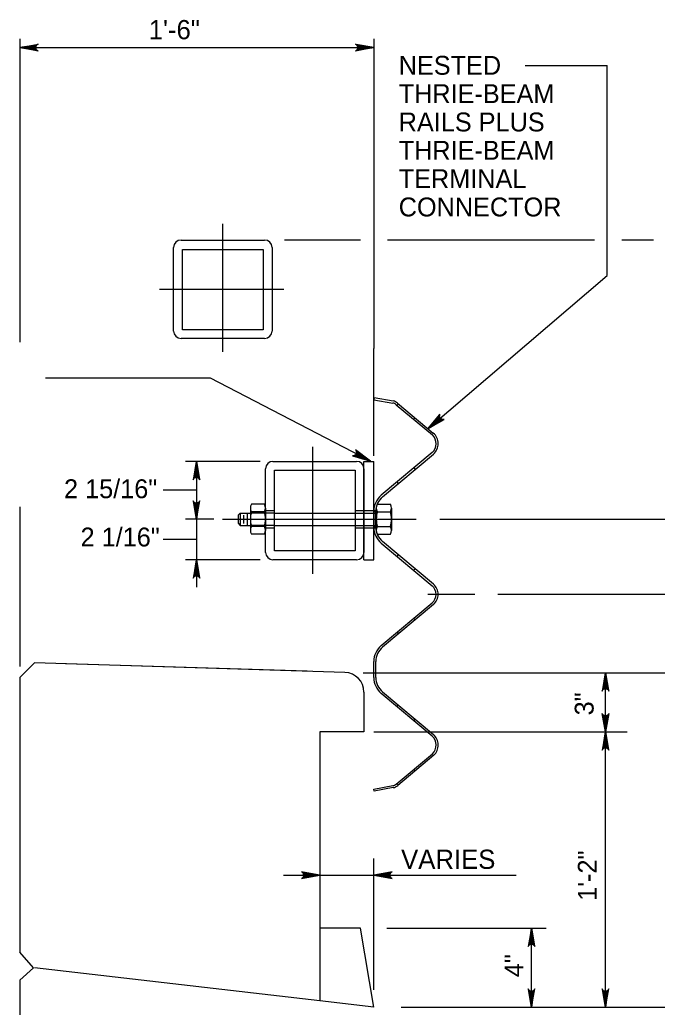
# Model space of a CAD drawing. Extents: x 632007860 to 635435983, y 295418622 to 297794622.
# Drawn here: x 633825946 to 633928846, y 296133282 to 296292631 of the extents above; entities that cross this region are included whole.
import ezdxf

# ---------------------------------------------------------------- set-up
doc = ezdxf.new("R2010")
doc.units = 0
for name, color, linetype in [('8', 7, 'Continuous'), ('S-ABUT', 7, 'Continuous'), ('S-DECK', 7, 'Continuous'), ('S-DETL-DIMS', 7, 'Continuous'), ('S-DETL-T120', 7, 'Continuous'), ('S-STEL', 7, 'Continuous')]:
    doc.layers.add(name, color=color, linetype=linetype)

msp = doc.modelspace()

# ---------------------------------------------------------------- linework, layer by layer
at = {"layer": '8'}
for p, q in [((633858727, 296239031), (633858727, 296259693)), ((633848498, 296249148), (633868578, 296249148)), ((633873268, 296203219), (633873268, 296223704)), ((633858691, 296212039), (633889941, 296212039)), ((633891801, 296199934), (633899397, 296199934))]:
    msp.add_line(p, q, dxfattribs=at)
at = {"layer": 'S-ABUT'}
for p, q in [((633828181, 296139661), (633825946, 296142171)), ((633825946, 296137671), (633828181, 296139661))]:
    msp.add_line(p, q, dxfattribs=at)
at = {"layer": 'S-DECK'}
for p, q in [((633828327, 296188859), (633825946, 296186477)), ((633878430, 296187309), (633828327, 296188859)), ((633825946, 296186477), (633825946, 296142171)), ((633881507, 296184136), (633881507, 296177732)), ((633874364, 296177732), (633874364, 296134296)), ((633881507, 296177732), (633874364, 296177732)), ((633880967, 296146039), (633874364, 296146039)), ((633883096, 296133282), (633880967, 296146039)), ((633874364, 296134296), (633828322, 296139645)), ((633825946, 296137671), (633825946, 296107186)), ((633883096, 296133282), (633874364, 296134296))]:
    msp.add_line(p, q, dxfattribs=at)
msp.add_arc((633878332, 296184136), 3175, 0, 88.22879, dxfattribs=at)
at = {"layer": 'S-DETL-DIMS'}
for p, q in [((633825946, 296289555), (633825946, 296268629)), ((633883096, 296289555), (633883096, 296239608)), ((633825946, 296288136), (633883096, 296288136)), ((633907523, 296285254), (633920786, 296285254)), ((633920786, 296251347), (633920786, 296285254)), ((633825946, 296268629), (633825946, 296240593)), ((633868663, 296257107), (633880958, 296257107)), ((633885291, 296257107), (633918740, 296257107)), ((633923144, 296257107), (633928239, 296257107)), ((633891854, 296226649), (633920786, 296251347)), ((633883094, 296222253), (633883094, 296239608)), ((633856711, 296234769), (633830120, 296234769)), ((633882538, 296221399), (633856711, 296234769)), ((633864738, 296221365), (633852720, 296221365)), ((633854466, 296221365), (633854466, 296201053)), ((633854466, 296216706), (633849079, 296216706)), ((633825946, 296214055), (633825946, 296188241)), ((633857273, 296212039), (633852720, 296212039)), ((633893768, 296212039), (633934041, 296212039)), ((633854466, 296208765), (633849079, 296208765)), ((633864738, 296205489), (633852720, 296205489)), ((633903112, 296199957), (633961692, 296199957)), ((633913164, 296199957), (633932328, 296199957)), ((633881361, 296187270), (633955531, 296187270)), ((633920483, 296133282), (633920483, 296187270)), ((633883096, 296177732), (633923989, 296177732)), ((633883096, 296136074), (633883096, 296157302)), ((633868536, 296154603), (633883096, 296154603)), ((633885675, 296154603), (633906053, 296154603)), ((633885176, 296146039), (633910942, 296146039)), ((633908544, 296133282), (633908544, 296146039)), ((633887495, 296133282), (633986864, 296133282))]:
    msp.add_line(p, q, dxfattribs=at)
for points in [[(633825946, 296288136), (633828905, 296288691), (633828791, 296288612), (633828677, 296288533), (633828618, 296288433), (633828559, 296288334), (633828542, 296288235), (633828525, 296288136), (633828542, 296288036), (633828559, 296287937), (633828618, 296287838), (633828677, 296287739), (633828791, 296287660), (633828905, 296287581), (633825946, 296288136), (633828791, 296287660), (633828677, 296287739), (633825946, 296288136), (633828618, 296287838), (633828559, 296287937), (633825946, 296288136), (633828542, 296288036), (633828525, 296288136), (633825946, 296288136), (633828542, 296288235), (633828559, 296288334), (633825946, 296288136), (633828618, 296288433), (633828677, 296288533), (633825946, 296288136), (633828791, 296288612)], [(633883096, 296288136), (633880137, 296287581), (633880251, 296287660), (633880365, 296287739), (633880424, 296287838), (633880483, 296287937), (633880500, 296288036), (633880517, 296288136), (633880500, 296288235), (633880483, 296288334), (633880424, 296288433), (633880365, 296288533), (633880251, 296288612), (633880137, 296288691), (633883096, 296288136), (633880251, 296288612), (633880365, 296288533), (633883096, 296288136), (633880424, 296288433), (633880483, 296288334), (633883096, 296288136), (633880500, 296288235), (633880517, 296288136), (633883096, 296288136), (633880500, 296288036), (633880483, 296287937), (633883096, 296288136), (633880424, 296287838), (633880365, 296287739), (633883096, 296288136), (633880251, 296287660)], [(633891854, 296226649), (633894465, 296228148), (633894327, 296228134), (633894189, 296228120), (633894080, 296228158), (633893970, 296228195), (633893893, 296228259), (633893816, 296228324), (633893764, 296228410), (633893713, 296228497), (633893693, 296228611), (633893673, 296228724), (633893709, 296228858), (633893744, 296228992), (633891854, 296226649), (633893709, 296228858), (633893673, 296228724), (633891854, 296226649), (633893693, 296228611), (633893713, 296228497), (633891854, 296226649), (633893764, 296228410), (633893816, 296228324), (633891854, 296226649), (633893893, 296228259), (633893970, 296228195), (633891854, 296226649), (633894080, 296228158), (633894189, 296228120), (633891854, 296226649), (633894327, 296228134)], [(633882538, 296221399), (633880165, 296223252), (633880230, 296223130), (633880295, 296223007), (633880302, 296222892), (633880308, 296222777), (633880278, 296222681), (633880247, 296222585), (633880187, 296222505), (633880126, 296222424), (633880028, 296222363), (633879930, 296222302), (633879793, 296222284), (633879655, 296222267), (633882538, 296221399), (633879793, 296222284), (633879930, 296222302), (633882538, 296221399), (633880028, 296222363), (633880126, 296222424), (633882538, 296221399), (633880187, 296222505), (633880247, 296222585), (633882538, 296221399), (633880278, 296222681), (633880308, 296222777), (633882538, 296221399), (633880302, 296222892), (633880295, 296223007), (633882538, 296221399), (633880230, 296223130)], [(633854466, 296221365), (633853911, 296218406), (633853990, 296218520), (633854069, 296218634), (633854168, 296218693), (633854267, 296218752), (633854367, 296218769), (633854466, 296218786), (633854565, 296218769), (633854664, 296218752), (633854763, 296218693), (633854863, 296218634), (633854942, 296218520), (633855021, 296218406), (633854466, 296221365), (633854942, 296218520), (633854863, 296218634), (633854466, 296221365), (633854763, 296218693), (633854664, 296218752), (633854466, 296221365), (633854565, 296218769), (633854466, 296218786), (633854466, 296221365), (633854367, 296218769), (633854267, 296218752), (633854466, 296221365), (633854168, 296218693), (633854069, 296218634), (633854466, 296221365), (633853990, 296218520)], [(633854466, 296212039), (633855021, 296214998), (633854942, 296214884), (633854863, 296214770), (633854763, 296214711), (633854664, 296214652), (633854565, 296214635), (633854466, 296214618), (633854367, 296214635), (633854267, 296214652), (633854168, 296214711), (633854069, 296214770), (633853990, 296214884), (633853911, 296214998), (633854466, 296212039), (633853990, 296214884), (633854069, 296214770), (633854466, 296212039), (633854168, 296214711), (633854267, 296214652), (633854466, 296212039), (633854367, 296214635), (633854466, 296214618), (633854466, 296212039), (633854565, 296214635), (633854664, 296214652), (633854466, 296212039), (633854763, 296214711), (633854863, 296214770), (633854466, 296212039), (633854942, 296214884)], [(633854466, 296205489), (633853911, 296202530), (633853990, 296202644), (633854069, 296202758), (633854168, 296202817), (633854267, 296202875), (633854367, 296202892), (633854466, 296202909), (633854565, 296202892), (633854664, 296202875), (633854763, 296202817), (633854863, 296202758), (633854942, 296202644), (633855021, 296202530), (633854466, 296205489), (633854942, 296202644), (633854863, 296202758), (633854466, 296205489), (633854763, 296202817), (633854664, 296202875), (633854466, 296205489), (633854565, 296202892), (633854466, 296202909), (633854466, 296205489), (633854367, 296202892), (633854267, 296202875), (633854466, 296205489), (633854168, 296202817), (633854069, 296202758), (633854466, 296205489), (633853990, 296202644)], [(633920483, 296187270), (633919928, 296184311), (633920007, 296184425), (633920086, 296184539), (633920186, 296184598), (633920285, 296184656), (633920384, 296184673), (633920483, 296184690), (633920582, 296184673), (633920682, 296184656), (633920781, 296184598), (633920880, 296184539), (633920959, 296184425), (633921038, 296184311), (633920483, 296187270), (633920959, 296184425), (633920880, 296184539), (633920483, 296187270), (633920781, 296184598), (633920682, 296184656), (633920483, 296187270), (633920582, 296184673), (633920483, 296184690), (633920483, 296187270), (633920384, 296184673), (633920285, 296184656), (633920483, 296187270), (633920186, 296184598), (633920086, 296184539), (633920483, 296187270), (633920007, 296184425)], [(633920483, 296177732), (633919928, 296180692), (633920007, 296180578), (633920086, 296180464), (633920186, 296180405), (633920285, 296180346), (633920384, 296180329), (633920483, 296180312), (633920582, 296180329), (633920682, 296180346), (633920781, 296180405), (633920880, 296180464), (633920959, 296180578), (633921038, 296180692), (633920483, 296177732), (633920959, 296180578), (633920880, 296180464), (633920483, 296177732), (633920781, 296180405), (633920682, 296180346), (633920483, 296177732), (633920582, 296180329), (633920483, 296180312), (633920483, 296177732), (633920384, 296180329), (633920285, 296180346), (633920483, 296177732), (633920186, 296180405), (633920086, 296180464), (633920483, 296177732), (633920007, 296180578)], [(633920483, 296177732), (633919928, 296174773), (633920007, 296174887), (633920086, 296175001), (633920186, 296175060), (633920285, 296175119), (633920384, 296175136), (633920483, 296175153), (633920582, 296175136), (633920682, 296175119), (633920781, 296175060), (633920880, 296175001), (633920959, 296174887), (633921038, 296174773), (633920483, 296177732), (633920959, 296174887), (633920880, 296175001), (633920483, 296177732), (633920781, 296175060), (633920682, 296175119), (633920483, 296177732), (633920582, 296175136), (633920483, 296175153), (633920483, 296177732), (633920384, 296175136), (633920285, 296175119), (633920483, 296177732), (633920186, 296175060), (633920086, 296175001), (633920483, 296177732), (633920007, 296174887)], [(633874364, 296154603), (633871405, 296155158), (633871519, 296155079), (633871633, 296155000), (633871692, 296154901), (633871751, 296154801), (633871768, 296154702), (633871785, 296154603), (633871768, 296154504), (633871751, 296154405), (633871692, 296154305), (633871633, 296154206), (633871519, 296154127), (633871405, 296154048), (633874364, 296154603), (633871519, 296154127), (633871633, 296154206), (633874364, 296154603), (633871692, 296154305), (633871751, 296154405), (633874364, 296154603), (633871768, 296154504), (633871785, 296154603), (633874364, 296154603), (633871768, 296154702), (633871751, 296154801), (633874364, 296154603), (633871692, 296154901), (633871633, 296155000), (633874364, 296154603), (633871519, 296155079)], [(633883096, 296154603), (633886055, 296154048), (633885941, 296154127), (633885827, 296154206), (633885768, 296154305), (633885710, 296154405), (633885693, 296154504), (633885675, 296154603), (633885693, 296154702), (633885710, 296154801), (633885768, 296154901), (633885827, 296155000), (633885941, 296155079), (633886055, 296155158), (633883096, 296154603), (633885941, 296155079), (633885827, 296155000), (633883096, 296154603), (633885768, 296154901), (633885710, 296154801), (633883096, 296154603), (633885693, 296154702), (633885675, 296154603), (633883096, 296154603), (633885693, 296154504), (633885710, 296154405), (633883096, 296154603), (633885768, 296154305), (633885827, 296154206), (633883096, 296154603), (633885941, 296154127)], [(633908544, 296146039), (633907989, 296143079), (633908068, 296143193), (633908147, 296143307), (633908246, 296143366), (633908345, 296143425), (633908444, 296143442), (633908544, 296143459), (633908643, 296143442), (633908742, 296143425), (633908841, 296143366), (633908940, 296143307), (633909019, 296143193), (633909098, 296143079), (633908544, 296146039), (633909019, 296143193), (633908940, 296143307), (633908544, 296146039), (633908841, 296143366), (633908742, 296143425), (633908544, 296146039), (633908643, 296143442), (633908544, 296143459), (633908544, 296146039), (633908444, 296143442), (633908345, 296143425), (633908544, 296146039), (633908246, 296143366), (633908147, 296143307), (633908544, 296146039), (633908068, 296143193)], [(633908544, 296133282), (633909098, 296136242), (633909019, 296136128), (633908940, 296136014), (633908841, 296135955), (633908742, 296135896), (633908643, 296135879), (633908544, 296135862), (633908444, 296135879), (633908345, 296135896), (633908246, 296135955), (633908147, 296136014), (633908068, 296136128), (633907989, 296136242), (633908544, 296133282), (633908068, 296136128), (633908147, 296136014), (633908544, 296133282), (633908246, 296135955), (633908345, 296135896), (633908544, 296133282), (633908444, 296135879), (633908544, 296135862), (633908544, 296133282), (633908643, 296135879), (633908742, 296135896), (633908544, 296133282), (633908841, 296135955), (633908940, 296136014), (633908544, 296133282), (633909019, 296136128)], [(633920483, 296133282), (633921038, 296136242), (633920959, 296136128), (633920880, 296136014), (633920781, 296135955), (633920682, 296135896), (633920582, 296135879), (633920483, 296135862), (633920384, 296135879), (633920285, 296135896), (633920186, 296135955), (633920086, 296136014), (633920007, 296136128), (633919928, 296136242), (633920483, 296133282), (633920007, 296136128), (633920086, 296136014), (633920483, 296133282), (633920186, 296135955), (633920285, 296135896), (633920483, 296133282), (633920384, 296135879), (633920483, 296135862), (633920483, 296133282), (633920582, 296135879), (633920682, 296135896), (633920483, 296133282), (633920781, 296135955), (633920880, 296136014), (633920483, 296133282), (633920959, 296136128)]]:
    msp.add_lwpolyline(points, dxfattribs=at)
at = {"layer": 'S-STEL'}
for p, q in [((633850789, 296242396), (633850789, 296255897)), ((633851977, 296257084), (633865478, 296257084)), ((633866665, 296255897), (633866665, 296242396)), ((633852224, 296255581), (633865230, 296255581)), ((633852224, 296242575), (633852224, 296255581)), ((633865230, 296255581), (633865230, 296242575)), ((633865230, 296242575), (633852224, 296242575)), ((633865478, 296241208), (633851977, 296241208)), ((633883152, 296231655), (633883095, 296231322)), ((633883152, 296231655), (633883095, 296231322)), ((633883095, 296231322), (633886155, 296230777)), ((633883152, 296231655), (633886215, 296231110)), ((633883152, 296231655), (633886215, 296231110)), ((633886720, 296230518), (633892547, 296225629)), ((633886835, 296230415), (633887054, 296230676)), ((633886936, 296230775), (633892698, 296225940)), ((633889533, 296228152), (633889752, 296228413)), ((633892493, 296222784), (633884285, 296215890)), ((633884501, 296215634), (633892713, 296222530)), ((633866817, 296221365), (633880318, 296221365)), ((633881505, 296205489), (633881505, 296221365)), ((633881505, 296221365), (633883094, 296221365)), ((633883094, 296205489), (633883094, 296221365)), ((633865629, 296206677), (633865629, 296220178)), ((633867064, 296219930), (633880070, 296219930)), ((633867064, 296206924), (633867064, 296219930)), ((633880070, 296219930), (633880070, 296206924)), ((633881505, 296220178), (633881505, 296206677)), ((633889534, 296220305), (633889750, 296220047)), ((633886837, 296218040), (633887053, 296217783)), ((633865444, 296214440), (633863354, 296214440)), ((633883676, 296214440), (633885765, 296214440)), ((633861544, 296213031), (633861197, 296212685)), ((633861197, 296212685), (633861197, 296211392)), ((633861544, 296213031), (633863168, 296213031)), ((633861544, 296213031), (633861544, 296211046)), ((633862085, 296212689), (633862085, 296211325)), ((633862627, 296213031), (633862627, 296211046)), ((633863168, 296213839), (633863168, 296210236)), ((633867064, 296213031), (633863168, 296213031)), ((633865444, 296213241), (633863354, 296213241)), ((633865546, 296213426), (633867064, 296213426)), ((633865629, 296213839), (633865629, 296210236)), ((633867064, 296213031), (633880070, 296213031)), ((633880070, 296213426), (633883429, 296213426)), ((633880070, 296213031), (633883429, 296213031)), ((633883095, 296213340), (633883095, 296212039)), ((633883096, 296213261), (633883427, 296213261)), ((633883429, 296212039), (633883429, 296213340)), ((633883490, 296213839), (633883490, 296210236)), ((633883676, 296213241), (633885766, 296213241)), ((633885951, 296213839), (633885951, 296210236)), ((633861197, 296211392), (633861544, 296211046)), ((633883095, 296212039), (633883095, 296210730)), ((633883429, 296210730), (633883429, 296212039)), ((633861544, 296211046), (633863168, 296211046)), ((633867064, 296211046), (633863168, 296211046)), ((633865444, 296210836), (633863354, 296210836)), ((633865444, 296209635), (633863354, 296209635)), ((633865545, 296210652), (633867064, 296210652)), ((633867064, 296211046), (633880070, 296211046)), ((633880070, 296211046), (633883490, 296211046)), ((633880070, 296210652), (633883431, 296210652)), ((633883096, 296210816), (633883427, 296210816)), ((633883676, 296210836), (633885766, 296210836)), ((633883676, 296209635), (633885766, 296209635)), ((633884285, 296208184), (633892493, 296201287)), ((633892713, 296201541), (633884501, 296208435)), ((633880070, 296206924), (633867064, 296206924)), ((633880318, 296205489), (633866817, 296205489)), ((633881505, 296205489), (633883094, 296205489)), ((633886840, 296206027), (633887054, 296206280)), ((633889527, 296203750), (633889753, 296204019)), ((633884285, 296191638), (633892493, 296198535)), ((633892713, 296198281), (633884501, 296191387)), ((633889527, 296196072), (633889753, 296195803)), ((633886840, 296193795), (633887054, 296193542)), ((633883095, 296186481), (633883095, 296189091)), ((633883430, 296186481), (633883430, 296189091)), ((633872345, 296187495), (633833343, 296188702)), ((633884501, 296184188), (633892713, 296177292)), ((633892493, 296177038), (633884285, 296183931)), ((633886837, 296181782), (633887053, 296182038)), ((633889534, 296179517), (633889750, 296179775)), ((633886720, 296169303), (633892547, 296174192)), ((633892780, 296173944), (633886956, 296169056)), ((633889533, 296171670), (633889757, 296171403)), ((633883095, 296168500), (633886155, 296169044)), ((633883151, 296168173), (633883095, 296168500)), ((633886221, 296168717), (633883151, 296168173)), ((633886835, 296169406), (633887059, 296169139))]:
    msp.add_line(p, q, dxfattribs=at)
for centre, radius, start, end in [((633851977, 296255897), 1188, 90, 180), ((633865478, 296255897), 1188, 0, 90), ((633851977, 296242396), 1188, 180, 270), ((633865478, 296242396), 1188, 270, 0), ((633885949, 296229597), 1199, 49.98585, 79.94952), ((633885949, 296229597), 1537, 49.98585, 79.94952), ((633891235, 296224235), 1922, 310.96064, 46.62924), ((633891235, 296224235), 2247, 310.96064, 49.35868), ((633866817, 296220178), 1188, 90, 180), ((633880318, 296220178), 1188, 0, 90), ((633886428, 296213340), 3333, 130.01267, 180), ((633864234, 296213839), 1066, 145.7053, 214.2947), ((633864563, 296213839), 1066, 325.7053, 34.2947), ((633886428, 296213340), 2998, 130.01267, 180), ((633884556, 296213839), 1066, 145.7053, 214.2947), ((633884885, 296213839), 1066, 325.7053, 34.2947), ((633867160, 296212039), 3991, 162.47188, 197.52812), ((633861638, 296212039), 3991, 342.47188, 17.52812), ((633887482, 296212039), 3991, 162.47188, 197.52812), ((633881960, 296212039), 3991, 342.47188, 17.52812), ((633864234, 296210236), 1066, 145.7053, 214.2947), ((633864563, 296210236), 1066, 325.7053, 34.2947), ((633886428, 296210731), 3333, 180, 229.98733), ((633886428, 296210731), 2998, 180, 229.98733), ((633884556, 296210236), 1066, 145.7053, 214.2947), ((633884885, 296210236), 1066, 325.7053, 34.2947), ((633866817, 296206677), 1188, 180, 270), ((633880318, 296206677), 1188, 270, 0), ((633891235, 296199835), 2256, 1.90954, 49.03936), ((633891235, 296199835), 1922, 2.24211, 49.03936), ((633891235, 296199986), 1922, 310.96064, 357.75789), ((633891235, 296199986), 2256, 310.96064, 358.09046), ((633886428, 296189091), 3333, 130.01267, 180), ((633886428, 296189091), 2998, 130.01267, 180), ((633886428, 296186481), 3333, 180.00218, 229.98733), ((633886428, 296186481), 2998, 180, 229.98733), ((633891235, 296175586), 1922, 313.37076, 49.03936), ((633891235, 296175586), 2256, 313.37076, 49.03936), ((633885949, 296170225), 1199, 280.05048, 310.01415), ((633885969, 296170228), 1534, 280.02985, 309.99999)]:
    msp.add_arc(centre, radius, start, end, dxfattribs=at)

# ---------------------------------------------------------------- texts
at = {"layer": 'S-DETL-T120'}
for s, height, p in [('1\'-6"', 3102.3, (633846770, 296289482)), ('NESTED', 3048, (633887115, 296283754)), ('THRIE-BEAM', 3048, (633887115, 296279182)), ('RAILS PLUS', 3048, (633887115, 296274610)), ('THRIE-BEAM', 3048, (633887115, 296270038)), ('TERMINAL', 3048, (633887115, 296265466)), ('CONNECTOR', 3048, (633887115, 296260894)), ('2 15/16"', 3048, (633833095, 296215426)), ('2 1/16"', 3048, (633835766, 296207634)), ('VARIES', 3102.3, (633887502, 296155609))]:
    msp.add_text(s, height=height, dxfattribs=at).set_placement(p)
for s, p in [('3"', (633918573, 296180379)), ('1\'-2"', (633919082, 296150455)), ('4"', (633907239, 296138133))]:
    msp.add_text(s, height=3048, rotation=90, dxfattribs=at).set_placement(p)

doc.saveas('drawing.dxf')
